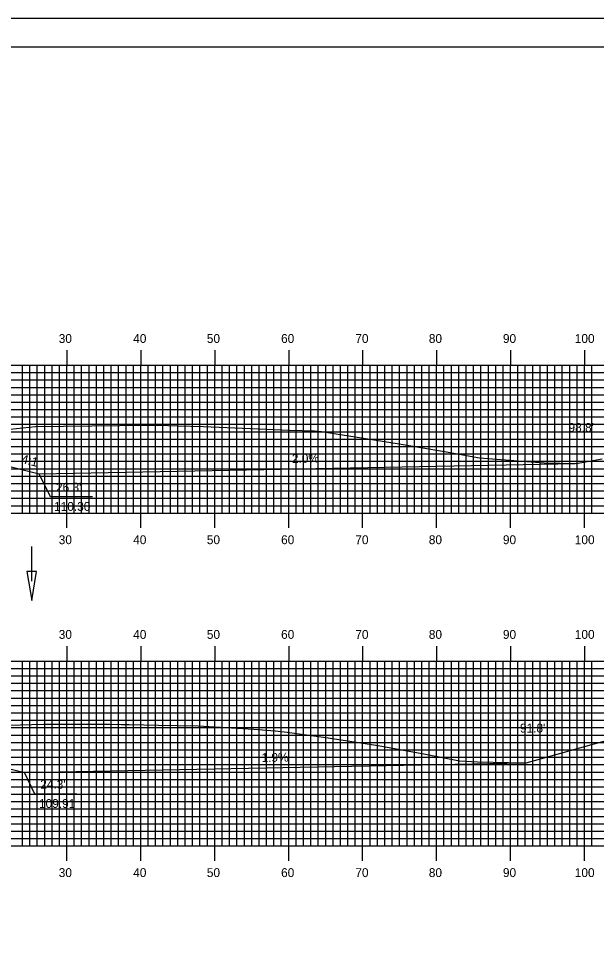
# Model space of a CAD drawing. Extents: x 1685586 to 1685929, y 461260 to 461480.
# Drawn here: x 1685775.2 to 1685853.4, y 461356.1 to 461480 of the extents above; entities that cross this region are included whole.
import ezdxf

# ---------------------------------------------------------------- set-up
doc = ezdxf.new("R2010")
doc.units = 0
for name, color, linetype in [('ANNOTATION', 7, 'Continuous'), ('BORDER', 7, 'Continuous'), ('D_Drainage_Ditch_Line', 7, 'Continuous'), ('D_Roadway_Centerline', 7, 'Continuous'), ('D_Roadway_SlopeLines', 7, 'Continuous'), ('D_Text_Standard', 7, 'Continuous'), ('H_V ANNOTATION', 7, 'Continuous'), ('M_Roadway_Centerline', 7, 'Continuous'), ('MAJOR', 7, 'Continuous'), ('MINOR', 7, 'Continuous'), ('PLOT BOUNDARY', 7, 'Continuous'), ('S_Roadway_Centerline', 7, 'Continuous')]:
    doc.layers.add(name, color=color, linetype=linetype)

msp = doc.modelspace()

# ---------------------------------------------------------------- linework, layer by layer
at = {"layer": 'ANNOTATION'}
for points in [[(1685785.22, 461415.25), (1685779.53, 461415.25), (1685778, 461418.37)], [(1685783.1, 461375.08), (1685777.41, 461375.08), (1685776, 461377.99)]]:
    msp.add_lwpolyline(points, dxfattribs=at)
at = {"layer": 'BORDER'}
msp.add_lwpolyline([(1685602.14, 461266.07), (1685922.14, 461266.07), (1685922.14, 461476.07), (1685602.14, 461476.07)], close=True, dxfattribs=at)
at = {"layer": 'D_Drainage_Ditch_Line'}
msp.add_line((1685777, 461403.87), (1685776.99, 461408.57), dxfattribs=at)
msp.add_lwpolyline([(1685777.65, 461405.18), (1685776.34, 461405.18), (1685776.99, 461401.25)], close=True, dxfattribs=at)
at = {"layer": 'D_Roadway_Centerline'}
msp.add_lwpolyline([(1685728.63, 461381.11), (1685735.74, 461382.89), (1685739.74, 461382.97), (1685751.74, 461382.42), (1685759.74, 461382.05), (1685772, 461378.99), (1685776, 461377.99), (1685843.58, 461379.3)], dxfattribs=at)
at = {"layer": 'D_Roadway_SlopeLines'}
for points in [[(1685761.74, 461422.44), (1685778, 461418.37)], [(1685778, 461418.37), (1685850.5, 461419.79)], [(1685778, 461418.37), (1685850.5, 461419.79)], [(1685778, 461418.37), (1685850.5, 461419.79)], [(1685778, 461418.37), (1685850.5, 461419.79)], [(1685759.74, 461382.05), (1685776, 461377.99)], [(1685776, 461377.99), (1685843.58, 461379.3)]]:
    msp.add_lwpolyline(points, dxfattribs=at)
at = {"layer": 'MAJOR'}
for p, q in [((1685781.74, 461435.08), (1685781.74, 461433.07)), ((1685791.74, 461435.08), (1685791.74, 461433.07)), ((1685801.74, 461435.08), (1685801.74, 461433.07)), ((1685811.74, 461435.08), (1685811.74, 461433.07)), ((1685821.74, 461435.08), (1685821.74, 461433.07)), ((1685831.74, 461435.08), (1685831.74, 461433.07)), ((1685841.74, 461435.08), (1685841.74, 461433.07)), ((1685851.74, 461435.08), (1685851.74, 461433.07)), ((1685611.74, 461433.07), (1685891.74, 461433.07)), ((1685611.74, 461433.07), (1685891.74, 461433.07)), ((1685781.74, 461413.07), (1685781.74, 461433.07)), ((1685791.74, 461413.07), (1685791.74, 461433.07)), ((1685801.74, 461413.07), (1685801.74, 461433.07)), ((1685811.74, 461413.07), (1685811.74, 461433.07)), ((1685821.74, 461413.07), (1685821.74, 461433.07)), ((1685831.74, 461413.07), (1685831.74, 461433.07)), ((1685841.74, 461413.07), (1685841.74, 461433.07)), ((1685851.74, 461413.07), (1685851.74, 461433.07)), ((1685611.74, 461428.07), (1685891.74, 461428.07)), ((1685611.74, 461423.07), (1685891.74, 461423.07)), ((1685611.74, 461418.07), (1685891.74, 461418.07)), ((1685611.74, 461413.07), (1685891.74, 461413.07)), ((1685611.74, 461413.07), (1685891.74, 461413.07)), ((1685781.74, 461411.07), (1685781.74, 461413.07)), ((1685791.74, 461411.07), (1685791.74, 461413.07)), ((1685801.74, 461411.07), (1685801.74, 461413.07)), ((1685811.74, 461411.07), (1685811.74, 461413.07)), ((1685821.74, 461411.07), (1685821.74, 461413.07)), ((1685831.74, 461411.07), (1685831.74, 461413.07)), ((1685841.74, 461411.07), (1685841.74, 461413.07)), ((1685851.74, 461411.07), (1685851.74, 461413.07)), ((1685781.74, 461395.08), (1685781.74, 461393.07)), ((1685791.74, 461395.08), (1685791.74, 461393.07)), ((1685801.74, 461395.08), (1685801.74, 461393.07)), ((1685811.74, 461395.08), (1685811.74, 461393.07)), ((1685821.74, 461395.08), (1685821.74, 461393.07)), ((1685831.74, 461395.08), (1685831.74, 461393.07)), ((1685841.74, 461395.08), (1685841.74, 461393.07)), ((1685851.74, 461395.08), (1685851.74, 461393.07)), ((1685611.74, 461393.07), (1685891.74, 461393.07)), ((1685611.74, 461393.07), (1685891.74, 461393.07)), ((1685781.74, 461368.07), (1685781.74, 461393.07)), ((1685791.74, 461368.07), (1685791.74, 461393.07)), ((1685801.74, 461368.07), (1685801.74, 461393.07)), ((1685811.74, 461368.07), (1685811.74, 461393.07)), ((1685821.74, 461368.07), (1685821.74, 461393.07)), ((1685831.74, 461368.07), (1685831.74, 461393.07)), ((1685841.74, 461368.07), (1685841.74, 461393.07)), ((1685851.74, 461368.07), (1685851.74, 461393.07)), ((1685611.74, 461388.07), (1685891.74, 461388.07)), ((1685611.74, 461383.07), (1685891.74, 461383.07)), ((1685611.74, 461378.07), (1685891.74, 461378.07)), ((1685611.74, 461373.07), (1685891.74, 461373.07)), ((1685611.74, 461368.07), (1685891.74, 461368.07)), ((1685611.74, 461368.07), (1685891.74, 461368.07)), ((1685781.74, 461366.07), (1685781.74, 461368.07)), ((1685791.74, 461366.07), (1685791.74, 461368.07)), ((1685801.74, 461366.07), (1685801.74, 461368.07)), ((1685811.74, 461366.07), (1685811.74, 461368.07)), ((1685821.74, 461366.07), (1685821.74, 461368.07)), ((1685831.74, 461366.07), (1685831.74, 461368.07)), ((1685841.74, 461366.07), (1685841.74, 461368.07)), ((1685851.74, 461366.07), (1685851.74, 461368.07))]:
    msp.add_line(p, q, dxfattribs=at)
at = {"layer": 'MINOR'}
for p, q in [((1685775.74, 461413.07), (1685775.74, 461433.07)), ((1685776.74, 461413.07), (1685776.74, 461433.07)), ((1685777.74, 461413.07), (1685777.74, 461433.07)), ((1685778.74, 461413.07), (1685778.74, 461433.07)), ((1685779.74, 461413.07), (1685779.74, 461433.07)), ((1685780.74, 461413.07), (1685780.74, 461433.07)), ((1685782.74, 461413.07), (1685782.74, 461433.07)), ((1685783.74, 461413.07), (1685783.74, 461433.07)), ((1685784.74, 461413.07), (1685784.74, 461433.07)), ((1685785.74, 461413.07), (1685785.74, 461433.07)), ((1685786.74, 461413.07), (1685786.74, 461433.07)), ((1685787.74, 461413.07), (1685787.74, 461433.07)), ((1685788.74, 461413.07), (1685788.74, 461433.07)), ((1685789.74, 461413.07), (1685789.74, 461433.07)), ((1685790.74, 461413.07), (1685790.74, 461433.07)), ((1685792.74, 461413.07), (1685792.74, 461433.07)), ((1685793.74, 461413.07), (1685793.74, 461433.07)), ((1685794.74, 461413.07), (1685794.74, 461433.07)), ((1685795.74, 461413.07), (1685795.74, 461433.07)), ((1685796.74, 461413.07), (1685796.74, 461433.07)), ((1685797.74, 461413.07), (1685797.74, 461433.07)), ((1685798.74, 461413.07), (1685798.74, 461433.07)), ((1685799.74, 461413.07), (1685799.74, 461433.07)), ((1685800.74, 461413.07), (1685800.74, 461433.07)), ((1685802.74, 461413.07), (1685802.74, 461433.07)), ((1685803.74, 461413.07), (1685803.74, 461433.07)), ((1685804.74, 461413.07), (1685804.74, 461433.07)), ((1685805.74, 461413.07), (1685805.74, 461433.07)), ((1685806.74, 461413.07), (1685806.74, 461433.07)), ((1685807.74, 461413.07), (1685807.74, 461433.07)), ((1685808.74, 461413.07), (1685808.74, 461433.07)), ((1685809.74, 461413.07), (1685809.74, 461433.07)), ((1685810.74, 461413.07), (1685810.74, 461433.07)), ((1685812.74, 461413.07), (1685812.74, 461433.07)), ((1685813.74, 461413.07), (1685813.74, 461433.07)), ((1685814.74, 461413.07), (1685814.74, 461433.07)), ((1685815.74, 461413.07), (1685815.74, 461433.07)), ((1685816.74, 461413.07), (1685816.74, 461433.07)), ((1685817.74, 461413.07), (1685817.74, 461433.07)), ((1685818.74, 461413.07), (1685818.74, 461433.07)), ((1685819.74, 461413.07), (1685819.74, 461433.07)), ((1685820.74, 461413.07), (1685820.74, 461433.07)), ((1685822.74, 461413.07), (1685822.74, 461433.07)), ((1685823.74, 461413.07), (1685823.74, 461433.07)), ((1685824.74, 461413.07), (1685824.74, 461433.07)), ((1685825.74, 461413.07), (1685825.74, 461433.07)), ((1685826.74, 461413.07), (1685826.74, 461433.07)), ((1685827.74, 461413.07), (1685827.74, 461433.07)), ((1685828.74, 461413.07), (1685828.74, 461433.07)), ((1685829.74, 461413.07), (1685829.74, 461433.07)), ((1685830.74, 461413.07), (1685830.74, 461433.07)), ((1685832.74, 461413.07), (1685832.74, 461433.07)), ((1685833.74, 461413.07), (1685833.74, 461433.07)), ((1685834.74, 461413.07), (1685834.74, 461433.07)), ((1685835.74, 461413.07), (1685835.74, 461433.07)), ((1685836.74, 461413.07), (1685836.74, 461433.07)), ((1685837.74, 461413.07), (1685837.74, 461433.07)), ((1685838.74, 461413.07), (1685838.74, 461433.07)), ((1685839.74, 461413.07), (1685839.74, 461433.07)), ((1685840.74, 461413.07), (1685840.74, 461433.07)), ((1685842.74, 461413.07), (1685842.74, 461433.07)), ((1685843.74, 461413.07), (1685843.74, 461433.07)), ((1685844.74, 461413.07), (1685844.74, 461433.07)), ((1685845.74, 461413.07), (1685845.74, 461433.07)), ((1685846.74, 461413.07), (1685846.74, 461433.07)), ((1685847.74, 461413.07), (1685847.74, 461433.07)), ((1685848.74, 461413.07), (1685848.74, 461433.07)), ((1685849.74, 461413.07), (1685849.74, 461433.07)), ((1685850.74, 461413.07), (1685850.74, 461433.07)), ((1685852.74, 461413.07), (1685852.74, 461433.07)), ((1685611.74, 461432.07), (1685891.74, 461432.07)), ((1685611.74, 461431.07), (1685891.74, 461431.07)), ((1685611.74, 461430.07), (1685891.74, 461430.07)), ((1685611.74, 461429.07), (1685891.74, 461429.07)), ((1685611.74, 461427.07), (1685891.74, 461427.07)), ((1685611.74, 461426.07), (1685891.74, 461426.07)), ((1685611.74, 461425.07), (1685891.74, 461425.07)), ((1685611.74, 461424.07), (1685891.74, 461424.07)), ((1685611.74, 461422.07), (1685891.74, 461422.07)), ((1685611.74, 461421.07), (1685891.74, 461421.07)), ((1685611.74, 461420.07), (1685891.74, 461420.07)), ((1685611.74, 461419.07), (1685891.74, 461419.07)), ((1685611.74, 461417.07), (1685891.74, 461417.07)), ((1685611.74, 461416.07), (1685891.74, 461416.07)), ((1685611.74, 461415.07), (1685891.74, 461415.07)), ((1685611.74, 461414.07), (1685891.74, 461414.07)), ((1685775.74, 461368.07), (1685775.74, 461393.07)), ((1685776.74, 461368.07), (1685776.74, 461393.07)), ((1685777.74, 461368.07), (1685777.74, 461393.07)), ((1685778.74, 461368.07), (1685778.74, 461393.07)), ((1685779.74, 461368.07), (1685779.74, 461393.07)), ((1685780.74, 461368.07), (1685780.74, 461393.07)), ((1685782.74, 461368.07), (1685782.74, 461393.07)), ((1685783.74, 461368.07), (1685783.74, 461393.07)), ((1685784.74, 461368.07), (1685784.74, 461393.07)), ((1685785.74, 461368.07), (1685785.74, 461393.07)), ((1685786.74, 461368.07), (1685786.74, 461393.07)), ((1685787.74, 461368.07), (1685787.74, 461393.07)), ((1685788.74, 461368.07), (1685788.74, 461393.07)), ((1685789.74, 461368.07), (1685789.74, 461393.07)), ((1685790.74, 461368.07), (1685790.74, 461393.07)), ((1685792.74, 461368.07), (1685792.74, 461393.07)), ((1685793.74, 461368.07), (1685793.74, 461393.07)), ((1685794.74, 461368.07), (1685794.74, 461393.07)), ((1685795.74, 461368.07), (1685795.74, 461393.07)), ((1685796.74, 461368.07), (1685796.74, 461393.07)), ((1685797.74, 461368.07), (1685797.74, 461393.07)), ((1685798.74, 461368.07), (1685798.74, 461393.07)), ((1685799.74, 461368.07), (1685799.74, 461393.07)), ((1685800.74, 461368.07), (1685800.74, 461393.07)), ((1685802.74, 461368.07), (1685802.74, 461393.07)), ((1685803.74, 461368.07), (1685803.74, 461393.07)), ((1685804.74, 461368.07), (1685804.74, 461393.07)), ((1685805.74, 461368.07), (1685805.74, 461393.07)), ((1685806.74, 461368.07), (1685806.74, 461393.07)), ((1685807.74, 461368.07), (1685807.74, 461393.07)), ((1685808.74, 461368.07), (1685808.74, 461393.07)), ((1685809.74, 461368.07), (1685809.74, 461393.07)), ((1685810.74, 461368.07), (1685810.74, 461393.07)), ((1685812.74, 461368.07), (1685812.74, 461393.07)), ((1685813.74, 461368.07), (1685813.74, 461393.07)), ((1685814.74, 461368.07), (1685814.74, 461393.07)), ((1685815.74, 461368.07), (1685815.74, 461393.07)), ((1685816.74, 461368.07), (1685816.74, 461393.07)), ((1685817.74, 461368.07), (1685817.74, 461393.07)), ((1685818.74, 461368.07), (1685818.74, 461393.07)), ((1685819.74, 461368.07), (1685819.74, 461393.07)), ((1685820.74, 461368.07), (1685820.74, 461393.07)), ((1685822.74, 461368.07), (1685822.74, 461393.07)), ((1685823.74, 461368.07), (1685823.74, 461393.07)), ((1685824.74, 461368.07), (1685824.74, 461393.07)), ((1685825.74, 461368.07), (1685825.74, 461393.07)), ((1685826.74, 461368.07), (1685826.74, 461393.07)), ((1685827.74, 461368.07), (1685827.74, 461393.07)), ((1685828.74, 461368.07), (1685828.74, 461393.07)), ((1685829.74, 461368.07), (1685829.74, 461393.07)), ((1685830.74, 461368.07), (1685830.74, 461393.07)), ((1685832.74, 461368.07), (1685832.74, 461393.07)), ((1685833.74, 461368.07), (1685833.74, 461393.07)), ((1685834.74, 461368.07), (1685834.74, 461393.07)), ((1685835.74, 461368.07), (1685835.74, 461393.07)), ((1685836.74, 461368.07), (1685836.74, 461393.07)), ((1685837.74, 461368.07), (1685837.74, 461393.07)), ((1685838.74, 461368.07), (1685838.74, 461393.07)), ((1685839.74, 461368.07), (1685839.74, 461393.07)), ((1685840.74, 461368.07), (1685840.74, 461393.07)), ((1685842.74, 461368.07), (1685842.74, 461393.07)), ((1685843.74, 461368.07), (1685843.74, 461393.07)), ((1685844.74, 461368.07), (1685844.74, 461393.07)), ((1685845.74, 461368.07), (1685845.74, 461393.07)), ((1685846.74, 461368.07), (1685846.74, 461393.07)), ((1685847.74, 461368.07), (1685847.74, 461393.07)), ((1685848.74, 461368.07), (1685848.74, 461393.07)), ((1685849.74, 461368.07), (1685849.74, 461393.07)), ((1685850.74, 461368.07), (1685850.74, 461393.07)), ((1685852.74, 461368.07), (1685852.74, 461393.07)), ((1685611.74, 461392.07), (1685891.74, 461392.07)), ((1685611.74, 461391.07), (1685891.74, 461391.07)), ((1685611.74, 461390.07), (1685891.74, 461390.07)), ((1685611.74, 461389.07), (1685891.74, 461389.07)), ((1685611.74, 461387.07), (1685891.74, 461387.07)), ((1685611.74, 461386.07), (1685891.74, 461386.07)), ((1685611.74, 461385.07), (1685891.74, 461385.07)), ((1685611.74, 461384.07), (1685891.74, 461384.07)), ((1685611.74, 461382.07), (1685891.74, 461382.07)), ((1685611.74, 461381.07), (1685891.74, 461381.07)), ((1685611.74, 461380.07), (1685891.74, 461380.07)), ((1685611.74, 461379.07), (1685891.74, 461379.07)), ((1685611.74, 461377.07), (1685891.74, 461377.07)), ((1685611.74, 461376.07), (1685891.74, 461376.07)), ((1685611.74, 461375.07), (1685891.74, 461375.07)), ((1685611.74, 461374.07), (1685891.74, 461374.07)), ((1685611.74, 461372.07), (1685891.74, 461372.07)), ((1685611.74, 461371.07), (1685891.74, 461371.07)), ((1685611.74, 461370.07), (1685891.74, 461370.07)), ((1685611.74, 461369.07), (1685891.74, 461369.07))]:
    msp.add_line(p, q, dxfattribs=at)
at = {"layer": 'PLOT BOUNDARY'}
msp.add_lwpolyline([(1685585.96, 461259.95), (1685925.96, 461259.95), (1685925.96, 461479.95), (1685585.96, 461479.95)], close=True, dxfattribs=at)
at = {"layer": 'S_Roadway_Centerline'}
for points in [[(1685774.07, 461424.42), (1685777.5, 461424.76), (1685788.9, 461424.9), (1685792.55, 461424.95), (1685793.56, 461424.95), (1685793.71, 461424.95), (1685793.76, 461424.95), (1685794.23, 461424.94), (1685796.73, 461424.88), (1685800.24, 461424.79), (1685811.87, 461424.29), (1685815.21, 461424.17), (1685815.75, 461424.14), (1685816.19, 461424.09), (1685826.39, 461422.46), (1685832.8, 461421.38), (1685837.53, 461420.54), (1685846.29, 461419.87), (1685850.63, 461419.79), (1685854.12, 461420.41)], [(1685772.21, 461384.35), (1685778.57, 461384.52), (1685786.15, 461384.53), (1685787.5, 461384.53), (1685789.12, 461384.49), (1685790.17, 461384.47), (1685794.15, 461384.42), (1685799.49, 461384.3), (1685807.02, 461383.85), (1685809.9, 461383.65), (1685811.53, 461383.47), (1685816.77, 461382.72), (1685823.83, 461381.64), (1685830.24, 461380.47), (1685834.86, 461379.6), (1685837.29, 461379.43), (1685843.58, 461379.3), (1685843.87, 461379.31), (1685853.04, 461381.89), (1685859.63, 461383.63)]]:
    msp.add_lwpolyline(points, dxfattribs=at)

# ---------------------------------------------------------------- texts
at = {"layer": 'ANNOTATION'}
for s, rotation, p in [('4:1', 345.9638, (1685775.5, 461419.86)), ('2.0%', 1.1218, (1685812.18, 461419.84)), ('1.9%', 1.1128, (1685808.08, 461379.41))]:
    msp.add_text(s, height=1.2, rotation=rotation, dxfattribs=at).set_placement(p)
for s, p in [("26.3' ", (1685780.27, 461415.97)), ('110.30', (1685780.01, 461413.37)), ("24.3' ", (1685778.14, 461375.81)), ('109.91', (1685777.97, 461373.21))]:
    msp.add_text(s, height=1.2, dxfattribs=at).set_placement(p)
at = {"layer": 'D_Text_Standard'}
for s, p in [("98.8'", (1685849.58, 461424.04)), ("91.8'", (1685843.02, 461383.41))]:
    msp.add_text(s, height=1.2, dxfattribs=at).set_placement(p)
at = {"layer": 'H_V ANNOTATION'}
for s, p in [('30', (1685780.64, 461436.07)), ('40', (1685790.71, 461436.07)), ('50', (1685800.67, 461436.07)), ('60', (1685810.71, 461436.07)), ('70', (1685820.75, 461436.07)), ('80', (1685830.69, 461436.07)), ('90', (1685840.71, 461436.07)), ('100', (1685850.43, 461436.07)), ('30', (1685780.64, 461408.87)), ('40', (1685790.71, 461408.87)), ('50', (1685800.67, 461408.87)), ('60', (1685810.71, 461408.87)), ('70', (1685820.75, 461408.87)), ('80', (1685830.69, 461408.87)), ('90', (1685840.71, 461408.87)), ('100', (1685850.43, 461408.87)), ('30', (1685780.64, 461396.07)), ('40', (1685790.71, 461396.07)), ('50', (1685800.67, 461396.07)), ('60', (1685810.71, 461396.07)), ('70', (1685820.75, 461396.07)), ('80', (1685830.69, 461396.07)), ('90', (1685840.71, 461396.07)), ('100', (1685850.43, 461396.07)), ('30', (1685780.64, 461363.87)), ('40', (1685790.71, 461363.87)), ('50', (1685800.67, 461363.87)), ('60', (1685810.71, 461363.87)), ('70', (1685820.75, 461363.87)), ('80', (1685830.69, 461363.87)), ('90', (1685840.71, 461363.87)), ('100', (1685850.43, 461363.87))]:
    msp.add_text(s, height=1.2, dxfattribs=at).set_placement(p)
at = {"layer": 'M_Roadway_Centerline'}
for s, p in [('C', (1685793.7, 461424.95)), ('L', (1685793.71, 461424.94)), ('C', (1685787.5, 461384.53)), ('L', (1685787.5, 461384.52))]:
    msp.add_text(s, height=0.0146, dxfattribs=at).set_placement(p)

doc.saveas('drawing.dxf')
